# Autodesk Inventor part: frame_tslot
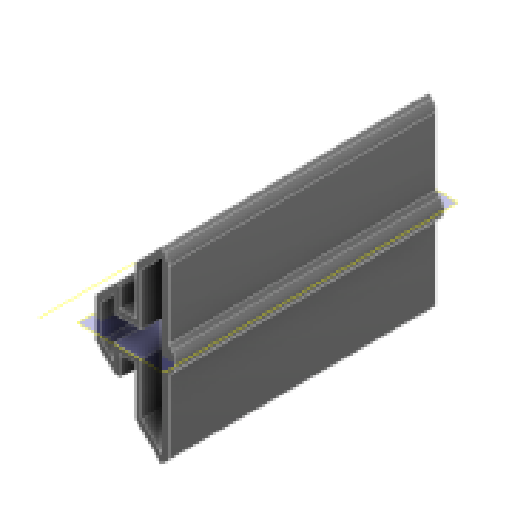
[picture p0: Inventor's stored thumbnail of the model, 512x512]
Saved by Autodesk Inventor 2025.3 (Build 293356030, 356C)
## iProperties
Created: 2026-03
Part Number: frame_tslot
Material: Plastica ABS
Document SubType Name: Modeling
Designer: R5800u
Density: 1.06 g/cm^3
Appearance: Liscia - Nero
Author: R5800u
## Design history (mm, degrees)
sketch "Schizzo1"
  geometry: L1 (7.61, 290.16)-(7.91, 289.64) reference; L2 (7.91, 289.64)-(7.61, 289.121) reference; L3 (7.61, 289.121)-(7.61, 286.701) reference; L4 (7.61, 286.701)-(4.549, 283.64) reference; L5 (4.549, 283.64)-(3.61, 283.64) reference; L6 (3.61, 283.64)-(3.61, 286.64) reference; L7 (3.61, 286.64)-(1.91, 286.64) reference; L8 (1.61, 286.34)-(1.61, 280.64) reference; L9 (2.61, 279.64)-(8.31, 279.64) reference; L10 (8.61, 279.94)-(8.61, 281.64) reference; L11 (8.61, 281.64)-(5.61, 281.64) reference; L12 (5.61, 281.64)-(5.61, 282.58) reference; L13 (5.61, 282.58)-(8.67, 285.64) reference; L14 (8.67, 285.64)-(11.09, 285.64) reference; L15 (11.09, 285.64)-(11.61, 285.94) reference; L16 (11.61, 285.94)-(12.129, 285.64) reference; L17 (12.129, 285.64)-(14.549, 285.64) reference; L18 (14.549, 285.64)-(17.61, 282.58) reference; L19 (17.61, 282.58)-(17.61, 281.64) reference; L20 (17.61, 281.64)-(14.61, 281.64) reference; L21 (14.61, 281.64)-(14.61, 279.94) reference; L22 (14.91, 279.64)-(20.61, 279.64) reference; L23 (21.61, 280.64)-(21.61, 286.34) reference; L24 (21.31, 286.64)-(19.61, 286.64) reference; L25 (19.61, 286.64)-(19.61, 283.64) reference; L26 (19.61, 283.64)-(18.67, 283.64) reference; L27 (18.67, 283.64)-(15.61, 286.701) reference; L28 (15.61, 286.701)-(15.61, 289.121) reference; L29 (15.61, 289.121)-(15.31, 289.64) reference; L30 (15.31, 289.64)-(15.61, 290.16) reference; L31 (15.61, 290.16)-(15.61, 292.58) reference; L32 (15.61, 292.58)-(18.67, 295.64) reference; L33 (18.67, 295.64)-(19.61, 295.64) reference; L34 (19.61, 295.64)-(19.61, 292.64) reference; L35 (19.61, 292.64)-(21.31, 292.64) reference; L36 (21.61, 292.94)-(21.61, 298.64) reference; L37 (20.61, 299.64)-(14.91, 299.64) reference; L38 (14.61, 299.34)-(14.61, 297.64) reference; L39 (14.61, 297.64)-(17.61, 297.64) reference; L40 (17.61, 297.64)-(17.61, 296.701) reference; L41 (17.61, 296.701)-(14.549, 293.64) reference; L42 (14.549, 293.64)-(12.129, 293.64) reference; L43 (12.129, 293.64)-(11.61, 293.34) reference; L44 (11.61, 293.34)-(11.09, 293.64) reference; L45 (11.09, 293.64)-(8.67, 293.64) reference; L46 (8.67, 293.64)-(5.61, 296.701) reference; L47 (5.61, 296.701)-(5.61, 297.64) reference; L48 (5.61, 297.64)-(8.61, 297.64) reference; L49 (8.61, 297.64)-(8.61, 299.34) reference; L50 (8.31, 299.64)-(2.61, 299.64) reference; L51 (1.61, 298.64)-(1.61, 292.94) reference; L52 (1.91, 292.64)-(3.61, 292.64) reference; L53 (3.61, 292.64)-(3.61, 295.64) reference; L54 (3.61, 295.64)-(4.549, 295.64) reference; L55 (4.549, 295.64)-(7.61, 292.58) reference; L56 (7.61, 292.58)-(7.61, 290.16) reference; L57 (21.71, 298.64)-(21.71, 292.94); L58 (21.31, 292.54)-(19.51, 292.54); L59 (19.51, 292.54)-(19.51, 295.54); L60 (19.51, 295.54)-(18.712, 295.54); L61 (18.712, 295.54)-(15.71, 292.538); L62 (15.71, 292.538)-(15.71, 290.133); L63 (15.71, 289.148)-(15.71, 286.742); L64 (15.71, 286.742)-(18.712, 283.74)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; C1 r 2.1 at (11.61, 289.64) reference; A1 r 0.3 centre (1.91, 286.34) between (1.91, 286.64) and (1.61, 286.34) reference; A2 r 1 centre (2.61, 280.64) between (1.61, 280.64) and (2.61, 279.64) reference; A3 r 0.3 centre (8.31, 279.94) between (8.31, 279.64) and (8.61, 279.94) reference; A4 r 0.3 centre (14.91, 279.94) between (14.61, 279.94) and (14.91, 279.64) reference; A5 r 1 centre (20.61, 280.64) between (20.61, 279.64) and (21.61, 280.64) reference; A6 r 0.3 centre (21.31, 286.34) between (21.61, 286.34) and (21.31, 286.64) reference; A7 r 0.3 centre (21.31, 292.94) between (21.31, 292.64) and (21.61, 292.94) reference; A8 r 1 centre (20.61, 298.64) between (21.61, 298.64) and (20.61, 299.64) reference; A9 r 0.3 centre (14.91, 299.34) between (14.91, 299.64) and (14.61, 299.34) reference; A10 r 0.3 centre (8.31, 299.34) between (8.61, 299.34) and (8.31, 299.64) reference; A11 r 1 centre (2.61, 298.64) between (2.61, 299.64) and (1.61, 298.64) reference; A12 r 0.3 centre (1.91, 292.94) between (1.61, 292.94) and (1.91, 292.64) reference; A13 r 0.4 centre (21.31, 286.34) between (21.71, 286.34) and (21.31, 286.74); A14 r 1.1 centre (20.61, 280.64) between (20.61, 279.54) and (21.71, 280.64); A15 r 0.4 centre (14.91, 279.94) between (14.51, 279.94) and (14.91, 279.54); A16 r 0.4 centre (8.31, 279.94) between (8.31, 279.54) and (8.71, 279.94); A17 r 1.1 centre (2.61, 280.64) between (1.51, 280.64) and (2.61, 279.54); A18 r 0.4 centre (1.91, 286.34) between (1.91, 286.74) and (1.51, 286.34); A19 r 0.4 centre (1.91, 292.94) between (1.51, 292.94) and (1.91, 292.54); A20 r 1.1 centre (2.61, 298.64) between (2.61, 299.74) and (1.51, 298.64); A21 r 0.4 centre (8.31, 299.34) between (8.71, 299.34) and (8.31, 299.74); A22 r 0.4 centre (14.91, 299.34) between (14.91, 299.74) and (14.51, 299.34); A23 r 1.1 centre (20.61, 298.64) between (21.71, 298.64) and (20.61, 299.74); 2 further points
  constraints: 126 end point, 22 point on circle, 11 centre point, 4 point on line, 3 vertical, 2 horizontal, 2 perpendicular, 1 midpoint, 63 other
  dimensions: "d0" = 0.1 distance between parallel lines of L36 L57; "d10" = 11 distance between parallel lines of L62 L117
extrude "Estrusione1" new body sketch "Schizzo1" distance "d1" = 40; taper "d2" = 0 deg
mirror "Speculare1"
feature "Svuotamento1" dims "d3" = 1
node "Piano di lavoro1"
node "Asse di lavoro1"
sketch "Schizzo2"
  geometry: L1 (26.71, 304.74)-(26.71, 274.54) reference; L2 (26.71, 302.619)-(25.649, 303.68); L3 (21.71, 299.74)-(26.71, 304.74) reference; 1 further point
  constraints: 2 end point, 2 point on line, 1 perpendicular
  dimensions: "d9" = 1.5 distance from line of L1.start L2
extrude "Estrusione2" cut sketch "Schizzo2" extent not by distance; stored distance "d7" = 0; taper "d8" = 0 deg
mirror "Speculare2"
sketch "Schizzo3"
  geometry: L1 (26.71, 276.662)-(26.71, 302.619) reference; L2 (26.71, 289.64)-(28.71, 289.64); L3 (28.71, 289.64)-(26.71, 291.64); L4 (28.71, 289.64)-(26.71, 287.64); 2 further points
  constraints: 6 end point, 1 horizontal, 1 midpoint, 1 point on line, 1 symmetric about line
  dimensions: "d11" = 2 distance of L2.start L2.end; "d12" = 2 distance from line of L2 L3.end
extrude "Estrusione3" join sketch "Schizzo3" stored distance "d13" = 2 (= d11); taper "d14" = 0 deg
fillet "Raccordo1" dims "d15" = 2
fillet "Raccordo2" dims "d16" = 2
node "Solido1"
node "Riferimento1"
